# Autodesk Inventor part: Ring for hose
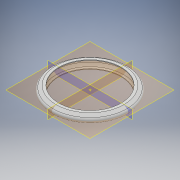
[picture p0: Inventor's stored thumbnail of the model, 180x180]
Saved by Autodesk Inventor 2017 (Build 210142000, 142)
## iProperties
Created: 2020-03
Part Number: Ring for hose
Material: Generic
Document SubType Name: Modeling
Designer: user
Density: 1 g/cm^3
Appearance: Default
Author: user
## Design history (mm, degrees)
sketch "Sketch1"
  geometry: L1 (12.7, 1.584)-(13.867, 0.845); L2 (13.867, -0.845)-(12.711, -1.577); L3 (0, 0)-(1.052, 0); L4 (12.7, 1.584)-(11.7, 1.584); L5 (12.711, -1.577)-(11.711, -1.577); L6 (11.711, -1.327)-(12.639, -1.327); L7 (12.639, -1.327)-(13.733, -0.634); L8 (13.733, 0.634)-(12.627, 1.334); L9 (12.627, 1.334)-(11.7, 1.334); L10 (11.7, 1.584)-(11.7, 1.334); L11 (11.711, -1.327)-(11.711, -1.577); L12 (0, -2.209)-(0, 2.216) reference; A1 r 1 centre (13.332, 0) between (13.867, -0.845) and (13.867, 0.845); A2 r 0.75 centre (13.332, 0) between (13.733, -0.634) and (13.733, 0.634); 1 further point
  constraints: 22 end point, 4 point on circle, 3 horizontal, 2 centre point, 2 point on line, 2 tangent, 1 parallel, 1 vertical, 5 other
  dimensions: "d1" = 3.16094 distance of L2.end L1.start; "d2" = 12.7 horizontal distance of L3.start L1.start; "d3" = 2.5 horizontal distance of L1.start point (15.2, 0); "d4" = 1 radius of A1; "d5" = 1 distance of L1.start L4.end; "d6" = 1 distance of L2.end L5.end; "d8" = 0.25 distance between parallel lines of L1 L8
revolve "Revolution1" sketch "Sketch1" stored, may be unused: angle "d9" = 90 deg
body "Solid1"
